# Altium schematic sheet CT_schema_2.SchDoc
size 271 x 273 mm
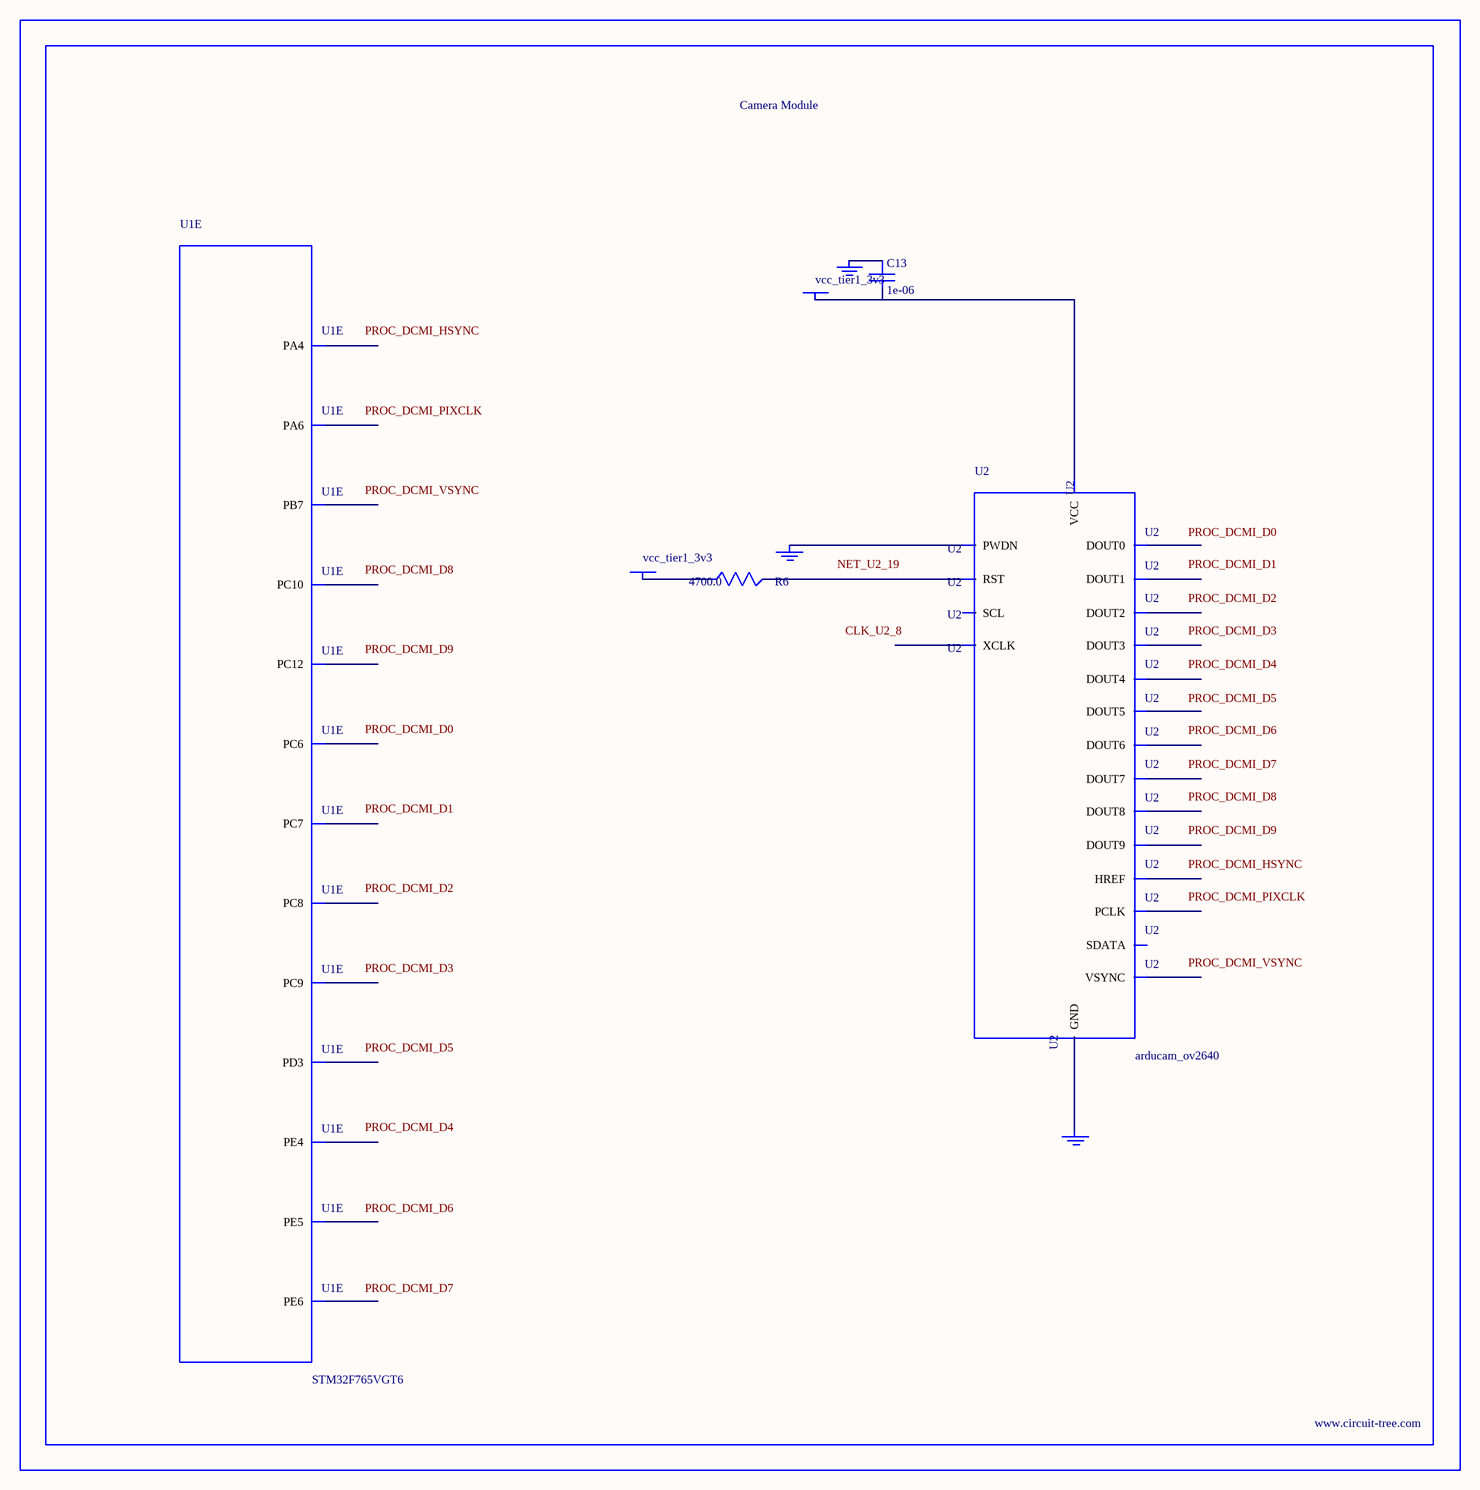
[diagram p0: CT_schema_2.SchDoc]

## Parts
BORDER1  (no value)
C13  1e-06  [C0603]
GND_INSTANCE_1_0  (no value)
GND_INSTANCE_1_1  (no value)
GND_INSTANCE_1_2  (no value)
POWER_INSTANCE_1_0  vcc_tier1_3v3
POWER_INSTANCE_1_1  vcc_tier1_3v3
R6  4700.0  [R0603]
U1  STM32F765VGT6  [LQFP100]  (part E of 8)
U2  arducam_ov2640  [ARDUCAM]

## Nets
NetC13_1: C13.1 GND_INSTANCE_1_0.0(GND)
NetC13_2: C13.2 POWER_INSTANCE_1_0.0(PWR) U2.1(VCC)
NetGND_INSTANCE_1_1_0: GND_INSTANCE_1_1.0(GND) U2.20(PWDN)
NetGND_INSTANCE_1_2_0: GND_INSTANCE_1_2.0(GND) U2.2(GND)
NetPOWER_INSTANCE_1_1_0: POWER_INSTANCE_1_1.0(PWR) R6.1
NetR6_2: R6.2 U2.19(RST)

Not connected (* = marked no-connect by the designer): U1 3(PE4) 4(PE5) 5(PE6) 28(PA4) 30(PA6) 63(PC6) 64(PC7) 65(PC8) 66(PC9) 78(PC10) 80(PC12) 84(PD3) 93(PB7); U2 3(SCL) 4(SDATA) 5(VSYNC) 6(HREF) 7(PCLK) 8(XCLK) 9(DOUT9) 10(DOUT8) 11(DOUT7) 12(DOUT6) 13(DOUT5) 14(DOUT4) 15(DOUT3) 16(DOUT2) 17(DOUT1) 18(DOUT0)

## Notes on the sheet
- Labels drawn without touching a wire or pin: CLK_U2_8, NET_U2_19, PROC_DCMI_D0, PROC_DCMI_D1, PROC_DCMI_D2, PROC_DCMI_D3, PROC_DCMI_D4, PROC_DCMI_D5, PROC_DCMI_D6, PROC_DCMI_D7, PROC_DCMI_D8, PROC_DCMI_D9, PROC_DCMI_HSYNC, PROC_DCMI_PIXCLK, PROC_DCMI_VSYNC

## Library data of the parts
BORDER1 = BORDER_PAGE1
C13 = C0603C105K3RACTU
GND_INSTANCE_1_0-GND_INSTANCE_1_2 = GND
POWER_INSTANCE_1_0 POWER_INSTANCE_1_1 = PWR
R6 = RC0603JR-074K7L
